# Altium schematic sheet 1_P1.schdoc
size 365 x 264 mm; Symbol: Drawing-Symbol_A4; Device: Drawing-Symbol_A4; Company: 嘉立创EDA; Version: V1.0; Page Size: A4; @Project Name: test1; @Page Count: 1; @Update Date: 2025-02-18; @Create Date: 2025-02-10; @Schematic Name: Schematic1; @Page No: 1; @Page Name: P1; @Create Time: 19:53:23; @Update Time: 22:31:19; Width: 1400; Height: 1000; Region Start: 1; X Region Count: 6; Y Region Count: 4; Blade Width: 10; Title Block Position: 3; @Board Name: Board1
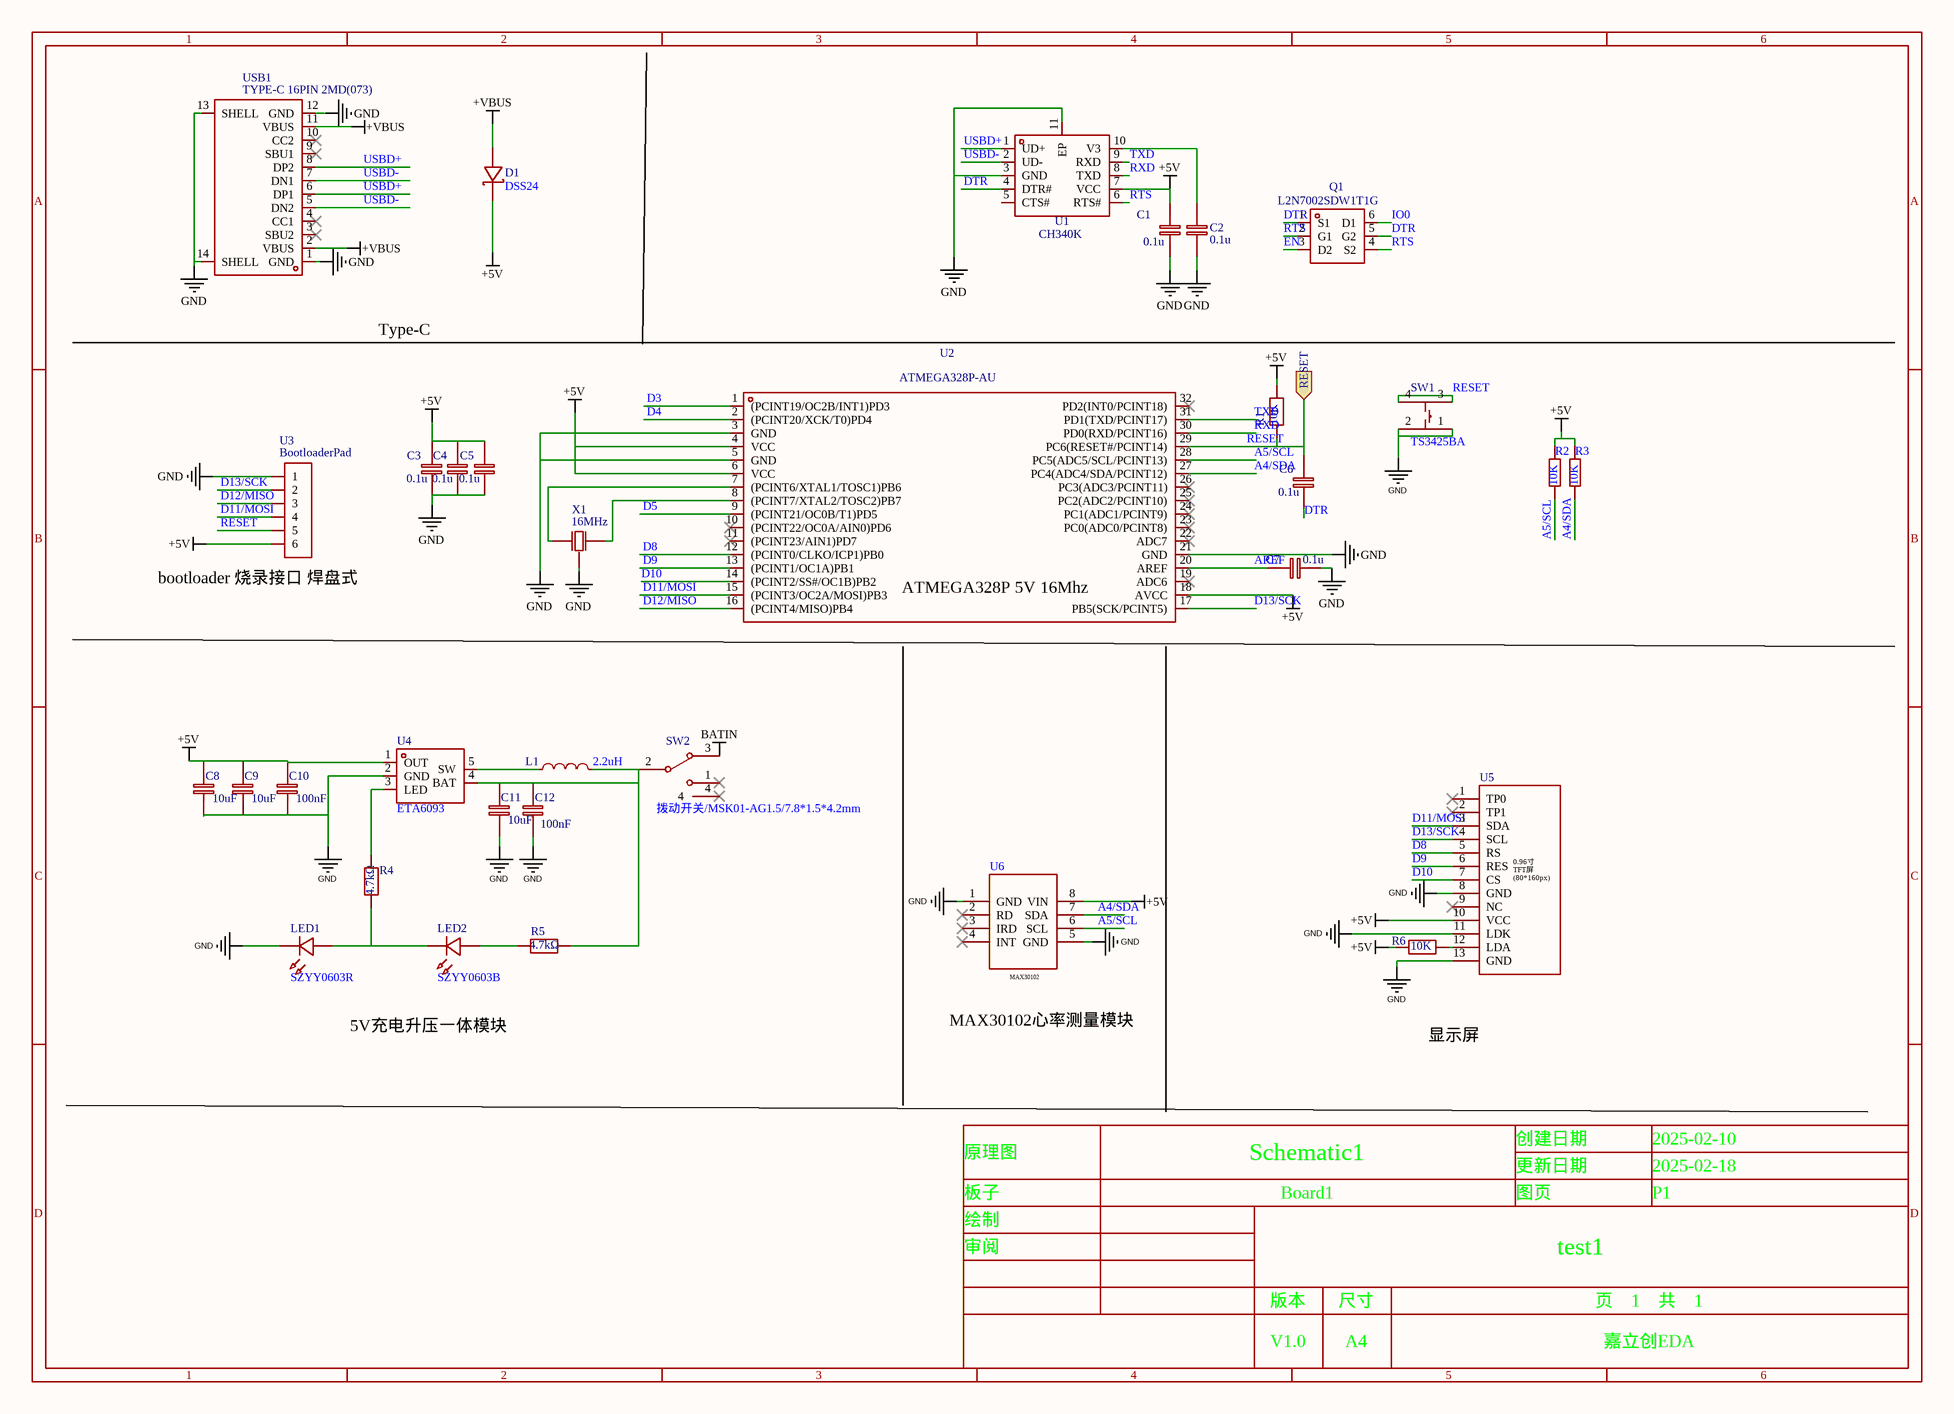
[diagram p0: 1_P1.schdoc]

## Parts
C1  0.1u  [C0603]
C2  0.1u  [C0603]
C3  0.1u  [C0603]
C4  0.1u  [C0603]
C5  0.1u  [C0603]
C6  0.1u  [C0603]
C7  0.1u  [C0603]
C8  10uF  [C0603]
C9  10uF  [C0603]
C10  100nF  [C0603]
C11  10uF  [C0603]
C12  100nF  [C0603]
D1  DSS24  [SOD-123_L2.8-W1.8-LS3.7-RD]
L1  2.2uH  [IND-SMD_L3.0-W3.0_FNR30XXS]
LED1  SZYY0603R  [LED0603_BLUE]
LED2  SZYY0603B  [LED0603_BLUE]
Q1  L2N7002SDW1T1G  [SOT-363_L2.0-W1.3-P0.65-LS2.1-BL]
R1  10K  [R0603]
R2  10K  [R0603]
R3  10K  [R0603]
R4  4.7kΩ  [R0603]
R5  4.7kΩ  [R0603]
R6  10K  [R0603]
SW1  TS3425BA  [SW-SMD_4P-L4.2-W3.2-P2.15-LS4.6-1]
SW2  拨动开关/MSK01-AG1.5/7.8*1.5*4.2mm  [SW-TH_MSK01-AG1.5]
U1  CH340K  [ESOP-10_L4.9-W3.9-P1.00-LS6.0-BL-EP]
U2  ATMEGA328P-AU  [TQFP-32_L7.0-W7.0-P0.80-LS9.0-BL]
U3  BootloaderPad  [BOOTLOADER]
U4  ETA6093  [SOT-23-5_L2.9-W1.6-P0.95-LS2.8-BR]
U5  (no value)  [0.96寸TFT屏幕焊接式]
U6  (no value)  [MAX30102]
USB1  TYPE-C 16PIN 2MD(073)  [USB-C-SMD_TYPE-C-6PIN-2MD-073]
X1  16MHz  [OSC-SMD_3P-L3.2-W1.3-P1.2-L]

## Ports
RESET (in)

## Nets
+5V: C1.2 C3.2 C4.2 C5.2 C8.2 C9.2 C10.2 D1.1(C) R1.2 R2.1 R3.1 R6.2 U1.7(VCC) U2.4(VCC) U2.6(VCC) U2.18(AVCC) U3.6 U4.1(OUT) U5.10(VCC) U6.8(VIN)
+VBUS: D1.2(A) USB1.2(VBUS) USB1.11(VBUS)
BATIN: SW2.3
GND: C1.1 C2.1 C3.1 C4.1 C5.1 C7.1 C8.1 C9.1 C10.1 C11.1 C12.1 LED1.1(C) SW1.1 SW1.2 U1.3(GND) U1.11(EP) U2.3(GND) U2.5(GND) U2.21(GND) U3.1 U4.2(GND) U5.8(GND) U5.11(LDK) U5.13(GND) U6.1(GND) U6.5(GND) USB1.1(GND) USB1.12(GND) USB1.13(SHELL) USB1.14(SHELL) X1.2(GND)
A4/SDA: R3.2 U2.27(PC4(ADC4/SDA/PCINT12)) U6.7(SDA)
A5/SCL: R2.2 U2.28(PC5(ADC5/SCL/PCINT13)) U6.6(SCL)
AREF: C7.2 U2.20(AREF)
D3: U2.1((PCINT19/OC2B/INT1)PD3)
D4: U2.2((PCINT20/XCK/T0)PD4)
D5: U2.9((PCINT21/OC0B/T1)PD5)
D8: U2.12((PCINT0/CLKO/ICP1)PB0) U5.5(RS)
D9: U2.13((PCINT1/OC1A)PB1) U5.6(RES)
D10: U2.14((PCINT2/SS#/OC1B)PB2) U5.7(CS)
D11/MOSI: U2.15((PCINT3/OC2A/MOSI)PB3) U3.4 U5.3(SDA)
D12/MISO: U2.16((PCINT4/MISO)PB4) U3.3
D13/SCK: U2.17(PB5(SCK/PCINT5)) U3.2 U5.4(SCL)
DTR: C6.1 Q1.1(S1) Q1.5(G2) U1.4(DTR#)
EN: Q1.3(D2)
IO0: Q1.6(D1)
RESET: C6.2 R1.1 SW1.3 SW1.4 U2.29(PC6(RESET#/PCINT14)) U3.5 ; port RESET
RTS: Q1.2(G1) Q1.4(S2) U1.6(RTS#)
RXD: U1.8(TXD) U2.30(PD0(RXD/PCINT16))
TXD: U1.9(RXD) U2.31(PD1(TXD/PCINT17))
USBD+: U1.1(UD+) USB1.6(DP1) USB1.8(DP2)
USBD-: U1.2(UD-) USB1.5(DN2) USB1.7(DN1)
NetC2_2: C2.2 U1.10(V3)
NetC11_2: C11.2 C12.2 L1.2 R5.2 SW2.2 U4.4(BAT)
NetL1_1: L1.1 U4.5(SW)
NetLED1_2: LED1.2(A) LED2.1(C) R4.1
NetLED2_2: LED2.2(A) R5.1
NetR4_2: R4.2 U4.3(LED)
NetR6_1: R6.1 U5.12(LDA)
NetU2_7: U2.7((PCINT6/XTAL1/TOSC1)PB6) X1.3(OSC2)
NetU2_8: U2.8((PCINT7/XTAL2/TOSC2)PB7) X1.1(OSC1)

Not connected (* = marked no-connect by the designer): SW2 1* 4*; U1 5(CTS#); U2 10((PCINT22/OC0A/AIN0)PD6)* 11((PCINT23/AIN1)PD7)* 19(ADC6)* 22(ADC7)* 23(PC0(ADC0/PCINT8))* 24(PC1(ADC1/PCINT9))* 25(PC2(ADC2/PCINT10))* 26(PC3(ADC3/PCINT11))* 32(PD2(INT0/PCINT18))*; U5 1(TP0)* 2(TP1)* 9(NC)*; U6 2(RD)* 3(IRD)* 4(INT)*; USB1 3(SBU2)* 4(CC1)* 9(SBU1)* 10(CC2)*

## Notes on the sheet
- Type-C
- (near U3) bootloader 烧录接口 焊盘式
- (near U2) ATMEGA328P 5V 16Mhz
- 5V充电升压一体模块
- MAX30102心率测量模块
- 显示屏

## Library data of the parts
C1-C7 = 0.1u: Convert to PCB: yes
C8 C9 C11 = CL10A106MA8NRNC: Manufacturer: SAMSUNG(三星); Symbol: 1u; Add into BOM: yes; Tolerance: ±20%; Voltage Rated: 25V; Temperature Coefficient: X5R
C10 = CC0603KRX7R9BB104: Manufacturer: YAGEO(国巨); Symbol: 1u; Add into BOM: yes; Tolerance: ±10%; Voltage Rated: 50V; Temperature Coefficient: X7R
C12 = CC0603KRX7R9BB104: Manufacturer: YAGEO(国巨); Symbol: 0.1u; Add into BOM: yes; Tolerance: ±10%; Voltage Rated: 50V; Temperature Coefficient: X7R
D1 = DSS24: Manufacturer: BORN(伯恩半导体); Symbol: DSS24_C511865; Add into BOM: yes; Forward Voltage (Vf@If): 550mV@2A; Reverse Voltage (Vr): 40V; Average Rectified Current (Io): 2A
L1 = FNR3015S2R2MT: Manufacturer: cjiang(长江微电); Add into BOM: yes; Tolerance: ±20%; Rated Current: 2A; DC Resistance (DCR): 78mΩ
LED1 = SZYY0603R: Manufacturer: yongyu(永裕光电); Symbol: LED_R; Convert to PCB: yes; Emitted Color: 红灯; Lens Color: 无色透明; Dominant Wavelength: 615nm~630nm; Peak Wavelength: 645nm; Forward Current: 20mA; Power Dissipation: 40mW; Viewing Angle: 120°
LED2 = SZYY0603B: Manufacturer: yongyu(永裕光电); Symbol: LED_B; Convert to PCB: yes; Emitted Color: 蓝灯; Lens Color: 无色透明; Dominant Wavelength: 460nm~475nm; Peak Wavelength: 469nm; Forward Current: 5mA; Power Dissipation: 100mW; Viewing Angle: 120°
Q1 = L2N7002SDW1T1G: Manufacturer: LRC(乐山无线电); Add into BOM: yes; Type: N沟道; Drain Source Voltage (Vdss): 60V; Continuous Drain Current (Id): 320mA; Power Dissipation (Pd): 300mW; Drain Source On Resistance (RDS(on)@Vgs,Id): 2.8Ω@10V,500mA; Gate Threshold Voltage (Vgs(th)@Id): 2V@250uA
R1 R6 = 10K: Convert to PCB: yes
R2 R3 = Res_0603: Symbol: 电阻; Convert to PCB: yes
R4 R5 = 0603WAJ0472T5E: Manufacturer: UNI-ROYAL(厚声); Symbol: 10k; Add into BOM: yes; Tolerance: ±5%; Power(Watts): 100mW; Overload Voltage (Max): 75V; Temperature Coefficient: ±100ppm/℃
SW1 = TS3425BA: Manufacturer: SHOU HAN(首韩); Add into BOM: yes; Circuit: 单刀单掷; Actuator Style: 椭圆形按钮; Operating Force: 250gf; Switch Length: 4.2mm; Switch Width: 3.2mm; Switch Height: 2.5mm; Strike Gundam: 不带; Contact Current: 50mA; Voltage Rating (DC): 12V; Insulation Resistance: 100MΩ; Actuator/Cap Color: 白色; Pin Style: J型引脚; Mechanical Life: 10万次
SW2 = 拨动开关/MSK01-AG1.5/7.8*1.5*4.2mm: Add into BOM: yes
U1 = CH340K_C18208922: Manufacturer: WCH(南京沁恒); Add into BOM: yes; Origin Footprint: ESOP-10_L4.9-W3.9-P1.00-LS6.2-BL-EP
U2 = ATMEGA328P-AU: Manufacturer: MICROCHIP(美国微芯); Add into BOM: yes; CPU Core: AVR; Program Storage Size: 32KB; RAM Size: 2KB; GPIO Ports Number: 23; Operating Voltage Range: 1.8V~5.5V; CPU Maximum Speed: 20MHz; Program Memory Type: FLASH; EEPROM: 1KB; ADC (Bit): 10bit; Peripheral/Function: 看门狗；PWM；看门狗；PWM; Watchdog: 有
U3 = A2541WV-6P: Manufacturer: Changjiang Connectors; Convert to PCB: yes; Check: false
U4 = ETA6093: Add into BOM: yes
U5 = 0.96寸tft屏(80x160px): Pin Type: IN; Add into BOM: yes
U6 = MAX30102: Add into BOM: yes
USB1 = TYPE-C 16PIN 2MD(073): Manufacturer: SHOU HAN(首韩); Convert to PCB: yes
X1 = CSTNE16M0V530000R0: Manufacturer: Murata Electronics; Convert to PCB: yes; Check: false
